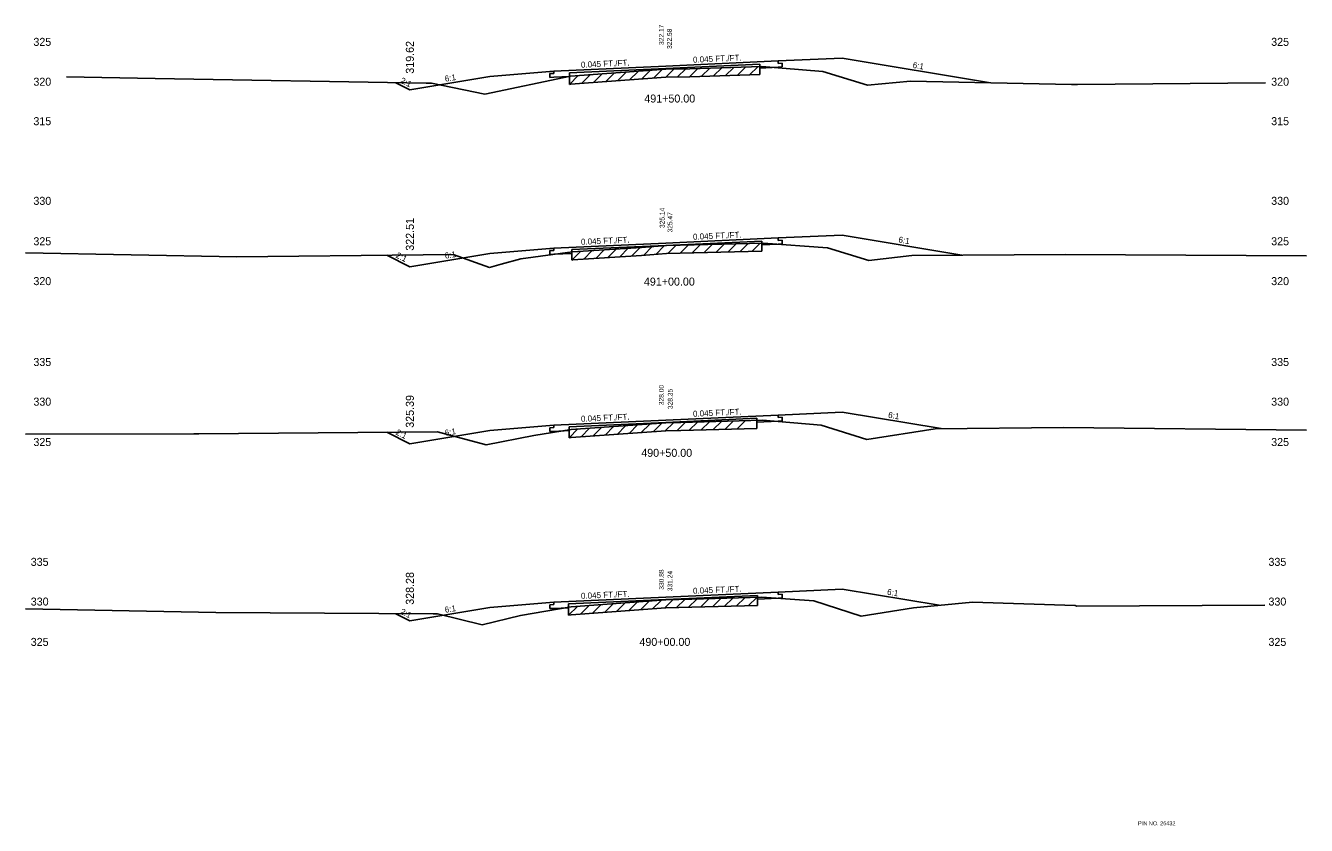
# Model space of a CAD drawing. Extents: x 883 to 1160, y 1002 to 4323.
# Drawn here: x 1000 to 1160, y 1102.7 to 1202.6 of the extents above; entities that cross this region are included whole.
import ezdxf

# ---------------------------------------------------------------- set-up
doc = ezdxf.new("R2010")
doc.units = 0
for name, color, linetype in [('Level 1', 7, 'Continuous'), ('Level 10', 7, 'Continuous'), ('Level 11', 7, 'Continuous'), ('Level 12', 7, 'Continuous'), ('Level 3', 7, 'Continuous'), ('Level 32', 7, 'Continuous'), ('Level 33', 7, 'Continuous'), ('Level 53', 7, 'Continuous'), ('Level 59', 7, 'Continuous'), ('Level 6', 7, 'Continuous'), ('Level 60', 7, 'Continuous'), ('Level 61', 7, 'Continuous'), ('Level 7', 7, 'Continuous')]:
    doc.layers.add(name, color=color, linetype=linetype)

msp = doc.modelspace()

# ---------------------------------------------------------------- linework, layer by layer
at = {"layer": 'Level 11'}
for p, q in [((1066, 1196.95), (1066, 1196.65)), ((1094, 1197.91), (1094, 1198.21)), ((1094.5, 1197.94), (1094, 1197.91)), ((1094, 1197.43), (1094.5, 1197.46)), ((1094.5, 1197.46), (1094.5, 1197.94)), ((1066, 1196.65), (1065.5, 1196.63)), ((1065.5, 1196.63), (1065.5, 1196.15)), ((1065.5, 1196.15), (1066, 1196.17)), ((1094, 1175.8), (1094, 1176.1)), ((1066, 1174.54), (1065.5, 1174.52)), ((1065.5, 1174.52), (1065.5, 1174.04)), ((1066, 1174.84), (1066, 1174.54)), ((1094.5, 1175.82), (1094, 1175.8)), ((1094, 1175.32), (1094.5, 1175.34)), ((1094.5, 1175.34), (1094.5, 1175.82)), ((1065.5, 1174.04), (1066, 1174.06)), ((1094, 1153.68), (1094, 1153.98)), ((1094.5, 1153.71), (1094, 1153.68)), ((1094.5, 1153.23), (1094.5, 1153.71)), ((1066, 1152.42), (1065.5, 1152.4)), ((1065.5, 1152.4), (1065.5, 1151.92)), ((1066, 1152.72), (1066, 1152.42)), ((1094, 1153.2), (1094.5, 1153.23)), ((1065.5, 1151.92), (1066, 1151.94)), ((1094, 1131.57), (1094, 1131.87)), ((1094.5, 1131.59), (1094, 1131.57)), ((1094.5, 1131.11), (1094.5, 1131.59)), ((1066, 1130.31), (1065.5, 1130.29)), ((1065.5, 1130.29), (1065.5, 1129.81)), ((1065.5, 1129.81), (1066, 1129.83)), ((1066, 1130.61), (1066, 1130.31)), ((1094, 1131.09), (1094.5, 1131.11))]:
    msp.add_line(p, q, dxfattribs=at)
at = {"layer": 'Level 12'}
for p, q in [((1091.74, 1197.51), (1091.74, 1197.33)), ((1091.74, 1197.33), (1094, 1197.43)), ((1067.94, 1196.26), (1066, 1196.17)), ((1067.94, 1196.28), (1067.94, 1196.26)), ((1091.96, 1175.45), (1091.96, 1175.23)), ((1091.96, 1175.23), (1094, 1175.32)), ((1068.22, 1174.16), (1066, 1174.06)), ((1068.22, 1174.34), (1068.22, 1174.16)), ((1067.89, 1152.03), (1066, 1151.94)), ((1067.89, 1152.13), (1067.89, 1152.03)), ((1091.36, 1153.32), (1091.36, 1153.09)), ((1091.36, 1153.09), (1094, 1153.2)), ((1091.41, 1131.2), (1091.41, 1130.97)), ((1067.82, 1129.91), (1066, 1129.83)), ((1067.82, 1129.97), (1067.82, 1129.91)), ((1091.41, 1130.97), (1094, 1131.09))]:
    msp.add_line(p, q, dxfattribs=at)
at = {"layer": 'Level 53'}
for p, q in [((1080, 1197.28), (1067.94, 1196.74)), ((1080, 1197.28), (1091.74, 1197.81)), ((1091.74, 1197.81), (1091.74, 1197.51)), ((1067.94, 1196.74), (1067.94, 1196.28)), ((1080, 1175.17), (1068.22, 1174.64)), ((1068.22, 1174.64), (1068.22, 1174.34)), ((1080, 1175.17), (1091.96, 1175.71)), ((1091.96, 1175.71), (1091.96, 1175.45)), ((1080, 1153.05), (1067.89, 1152.51)), ((1067.89, 1152.51), (1067.89, 1152.13)), ((1080, 1153.05), (1091.36, 1153.57)), ((1091.36, 1153.57), (1091.36, 1153.32)), ((1080, 1130.94), (1091.41, 1131.45)), ((1091.41, 1131.45), (1091.41, 1131.2)), ((1080, 1130.94), (1067.82, 1130.39)), ((1067.82, 1130.39), (1067.82, 1129.97))]:
    msp.add_line(p, q, dxfattribs=at)
at = {"layer": 'Level 59'}
for p, q in [((1066, 1196.95), (1080, 1197.58)), ((1080, 1197.58), (1094, 1198.21)), ((1080, 1175.47), (1094, 1176.1)), ((1066, 1174.84), (1080, 1175.47)), ((1080, 1153.35), (1094, 1153.98)), ((1066, 1152.72), (1080, 1153.35)), ((1066, 1130.61), (1080, 1131.24)), ((1080, 1131.24), (1094, 1131.87))]:
    msp.add_line(p, q, dxfattribs=at)
at = {"layer": 'Level 6'}
for p, q in [((1094, 1198.21), (1102, 1198.57)), ((1058, 1196.29), (1066, 1196.95)), ((1094, 1176.1), (1102, 1176.46)), ((1058, 1174.17), (1066, 1174.84)), ((1094, 1153.98), (1102, 1154.34)), ((1058, 1152.06), (1066, 1152.72)), ((1094, 1131.87), (1102, 1132.23)), ((1058, 1129.94), (1066, 1130.61))]:
    msp.add_line(p, q, dxfattribs=at)
at = {"layer": 'Level 60'}
for p, q in [((1068.05, 1196.3), (1080, 1197.17)), ((1080, 1197.17), (1082.97, 1197.25)), ((1082.97, 1197.25), (1091.97, 1197.52)), ((1091.97, 1197.52), (1099.59, 1196.9)), ((1099.59, 1196.9), (1105.18, 1195.19)), ((1005.12, 1196.22), (1016.19, 1196.04)), ((1016.19, 1196.04), (1050.02, 1195.43)), ((1050.02, 1195.43), (1050.7, 1195.42)), ((1050.7, 1195.42), (1057.37, 1194.06)), ((1057.37, 1194.06), (1068.05, 1196.3)), ((1105.18, 1195.19), (1110.56, 1195.68)), ((1110.56, 1195.68), (1130.65, 1195.29)), ((1130.65, 1195.29), (1131.42, 1195.28)), ((1131.42, 1195.28), (1154.89, 1195.47)), ((1068.33, 1174.35), (1076.93, 1174.93)), ((1076.93, 1174.93), (1080.06, 1175.14)), ((1080.06, 1175.14), (1092.13, 1175.45)), ((1092.13, 1175.45), (1100.17, 1174.86)), ((1100.17, 1174.86), (1105.35, 1173.27)), ((1000, 1174.26), (1026.38, 1173.76)), ((1026.38, 1173.76), (1049.66, 1173.99)), ((1049.66, 1173.99), (1053.43, 1174.03)), ((1053.43, 1174.03), (1057.97, 1172.41)), ((1057.97, 1172.41), (1059.41, 1172.81)), ((1059.41, 1172.81), (1061.86, 1173.5)), ((1061.86, 1173.5), (1068.33, 1174.35)), ((1105.35, 1173.27), (1110.72, 1173.93)), ((1110.72, 1173.93), (1129.85, 1174.03)), ((1129.85, 1174.03), (1160, 1173.88)), ((1063.49, 1151.42), (1068.16, 1152.18)), ((1068.16, 1152.18), (1080, 1153)), ((1080, 1153), (1081.85, 1153.05)), ((1081.85, 1153.05), (1092.04, 1153.34)), ((1092.04, 1153.34), (1099.38, 1152.72)), ((1099.38, 1152.72), (1105.07, 1150.94)), ((1105.07, 1150.94), (1113.62, 1152.27)), ((1113.62, 1152.27), (1129.64, 1152.41)), ((1129.64, 1152.41), (1160, 1152.09)), ((1000, 1151.58), (1021.01, 1151.64)), ((1021.01, 1151.64), (1021.62, 1151.63)), ((1021.62, 1151.63), (1051.47, 1151.89)), ((1051.47, 1151.89), (1057.55, 1150.25)), ((1057.55, 1150.25), (1063.49, 1151.42)), ((1083.23, 1130.97), (1091.96, 1131.22)), ((1091.96, 1131.22), (1098.47, 1130.79)), ((1000, 1129.76), (1023.77, 1129.32)), ((1061.84, 1128.93), (1068.15, 1130.03)), ((1068.15, 1130.03), (1080, 1130.88)), ((1080, 1130.88), (1083.23, 1130.97)), ((1098.47, 1130.79), (1104.4, 1128.85)), ((1104.4, 1128.85), (1110.9, 1129.89)), ((1110.9, 1129.89), (1118.31, 1130.61)), ((1118.31, 1130.61), (1131.1, 1130.2)), ((1131.1, 1130.2), (1131.32, 1130.09)), ((1131.32, 1130.09), (1154.83, 1130.24)), ((1023.77, 1129.32), (1050.93, 1129.13)), ((1050.93, 1129.13), (1051.47, 1129.13)), ((1051.47, 1129.13), (1057.02, 1127.76)), ((1057.02, 1127.76), (1061.84, 1128.93))]:
    msp.add_line(p, q, dxfattribs=at)
at = {"layer": 'Level 61'}
for p, q in [((1075.02, 1196.81), (1073.94, 1195.73)), ((1076.52, 1196.91), (1075.44, 1195.84)), ((1078.02, 1197.02), (1076.94, 1195.95)), ((1079.52, 1197.13), (1078.44, 1196.05)), ((1080.98, 1197.19), (1079.94, 1196.16)), ((1082.47, 1197.24), (1081.44, 1196.21)), ((1083.97, 1197.28), (1082.94, 1196.25)), ((1085.47, 1197.33), (1084.44, 1196.3)), ((1086.97, 1197.37), (1085.94, 1196.34)), ((1088.47, 1197.41), (1087.44, 1196.38)), ((1089.97, 1197.46), (1088.94, 1196.43)), ((1091.47, 1197.5), (1090.44, 1196.47)), ((1091.74, 1196.51), (1091.74, 1197.51)), ((1069.04, 1196.38), (1067.94, 1195.28)), ((1067.94, 1196.28), (1067.94, 1195.28)), ((1067.94, 1195.28), (1068.05, 1195.3)), ((1068.05, 1195.3), (1080, 1196.17)), ((1070.52, 1196.48), (1069.44, 1195.41)), ((1072.02, 1196.59), (1070.94, 1195.51)), ((1073.52, 1196.7), (1072.44, 1195.62)), ((1080, 1196.17), (1082.97, 1196.25)), ((1082.97, 1196.25), (1091.74, 1196.51)), ((1069.3, 1174.42), (1068.22, 1173.34)), ((1070.79, 1174.52), (1069.72, 1173.45)), ((1072.29, 1174.62), (1071.22, 1173.55)), ((1073.79, 1174.72), (1072.72, 1173.65)), ((1075.29, 1174.82), (1074.22, 1173.75)), ((1076.79, 1174.92), (1075.72, 1173.85)), ((1078.29, 1175.02), (1077.22, 1173.95)), ((1079.79, 1175.12), (1078.72, 1174.05)), ((1080.06, 1174.14), (1091.96, 1174.45)), ((1081.24, 1175.17), (1080.22, 1174.14)), ((1082.75, 1175.21), (1081.72, 1174.18)), ((1084.25, 1175.25), (1083.22, 1174.22)), ((1085.75, 1175.29), (1084.72, 1174.26)), ((1087.25, 1175.33), (1086.22, 1174.3)), ((1088.75, 1175.37), (1087.72, 1174.34)), ((1090.25, 1175.41), (1089.22, 1174.38)), ((1091.75, 1175.44), (1090.72, 1174.42)), ((1091.96, 1174.45), (1091.96, 1175.45)), ((1068.22, 1174.34), (1068.22, 1173.34)), ((1068.22, 1173.34), (1068.33, 1173.35)), ((1068.33, 1173.35), (1076.93, 1173.93)), ((1076.93, 1173.93), (1080.06, 1174.14)), ((1068.99, 1152.24), (1067.89, 1151.13)), ((1067.89, 1152.13), (1067.89, 1151.13)), ((1070.46, 1152.34), (1069.39, 1151.26)), ((1071.96, 1152.44), (1070.89, 1151.37)), ((1073.46, 1152.54), (1072.39, 1151.47)), ((1074.96, 1152.65), (1073.89, 1151.57)), ((1076.46, 1152.75), (1075.39, 1151.68)), ((1077.96, 1152.86), (1076.89, 1151.78)), ((1079.46, 1152.96), (1078.39, 1151.89)), ((1080.92, 1153.02), (1079.89, 1151.99)), ((1080, 1152), (1081.85, 1152.05)), ((1082.42, 1153.07), (1081.39, 1152.04)), ((1081.85, 1152.05), (1091.36, 1152.32)), ((1083.92, 1153.11), (1082.89, 1152.08)), ((1085.42, 1153.15), (1084.39, 1152.12)), ((1086.92, 1153.19), (1085.89, 1152.16)), ((1088.42, 1153.24), (1087.39, 1152.21)), ((1089.92, 1153.28), (1088.89, 1152.25)), ((1091.36, 1152.32), (1091.36, 1153.32)), ((1067.89, 1151.13), (1068.16, 1151.18)), ((1068.16, 1151.18), (1080, 1152)), ((1091.41, 1130.2), (1091.41, 1131.2)), ((1068.93, 1130.08), (1067.82, 1128.97)), ((1067.82, 1129.97), (1067.82, 1128.97)), ((1068.15, 1129.03), (1080, 1129.88)), ((1070.4, 1130.19), (1069.32, 1129.11)), ((1071.9, 1130.3), (1070.82, 1129.22)), ((1073.4, 1130.4), (1072.32, 1129.33)), ((1074.9, 1130.51), (1073.82, 1129.43)), ((1076.4, 1130.62), (1075.32, 1129.54)), ((1077.9, 1130.73), (1076.82, 1129.65)), ((1079.4, 1130.83), (1078.32, 1129.76)), ((1080.86, 1130.9), (1079.82, 1129.86)), ((1080, 1129.88), (1083.23, 1129.97)), ((1082.35, 1130.94), (1081.32, 1129.92)), ((1083.85, 1130.99), (1082.82, 1129.96)), ((1083.23, 1129.97), (1091.41, 1130.2)), ((1085.35, 1131.03), (1084.32, 1130)), ((1086.85, 1131.07), (1085.82, 1130.04)), ((1088.35, 1131.11), (1087.32, 1130.09)), ((1089.85, 1131.16), (1088.82, 1130.13)), ((1091.35, 1131.2), (1090.32, 1130.17)), ((1067.82, 1128.97), (1068.15, 1129.03))]:
    msp.add_line(p, q, dxfattribs=at)
at = {"layer": 'Level 7'}
for p, q in [((1102, 1198.57), (1120.52, 1195.49)), ((1046.25, 1195.49), (1048, 1194.62)), ((1048, 1194.62), (1058, 1196.29)), ((1102, 1176.46), (1116.96, 1173.97)), ((1045.12, 1173.94), (1048, 1172.51)), ((1048, 1172.51), (1058, 1174.17)), ((1102, 1154.34), (1114.39, 1152.28)), ((1048, 1150.39), (1058, 1152.06)), ((1045.11, 1151.84), (1048, 1150.39)), ((1102, 1132.23), (1114.14, 1130.21)), ((1048, 1128.28), (1058, 1129.94)), ((1046.23, 1129.16), (1048, 1128.28))]:
    msp.add_line(p, q, dxfattribs=at)

# ---------------------------------------------------------------- texts
at = {"layer": 'Level 1'}
for s, height, p in [('491+50.00', 1, (1077.29, 1193.02)), ('491+00.00', 1, (1077.24, 1170.15)), ('490+50.00', 1, (1076.91, 1148.76)), ('490+00.00', 1, (1076.68, 1125.14)), ('PIN NO. 26432', 0.5, (1138.97, 1102.73))]:
    msp.add_text(s, height=height, dxfattribs=at).set_placement(p)
at = {"layer": 'Level 10'}
for s, p in [('322.17', (1079.72, 1200.21)), ('325.14', (1079.82, 1177.34)), ('328.00', (1079.72, 1155.21)), ('330.88', (1079.72, 1132.16))]:
    msp.add_text(s, height=0.6, rotation=90, dxfattribs=at).set_placement(p)
at = {"layer": 'Level 3'}
for s, p in [(' 325', (1000.6, 1200.1)), (' 325', (1155.23, 1200.1)), (' 320', (1000.6, 1195.12)), (' 320', (1155.23, 1195.12)), (' 315', (1000.6, 1190.19)), (' 315', (1155.23, 1190.19)), (' 330', (1000.6, 1180.24)), (' 330', (1155.23, 1180.24)), (' 325', (1000.6, 1175.19)), (' 325', (1155.23, 1175.19)), (' 320', (1000.6, 1170.21)), (' 320', (1155.23, 1170.21)), (' 335', (1000.6, 1160.11)), (' 335', (1155.23, 1160.11)), (' 330', (1000.6, 1155.15)), (' 330', (1155.23, 1155.15)), (' 325', (1000.6, 1150.11)), (' 325', (1155.23, 1150.11)), (' 335', (1000.27, 1135.14)), (' 335', (1154.89, 1135.14)), (' 330', (1000.27, 1130.18)), (' 330', (1154.89, 1130.18)), (' 325', (1000.27, 1125.14)), (' 325', (1154.89, 1125.14))]:
    msp.add_text(s, height=1, dxfattribs=at).set_placement(p)
at = {"layer": 'Level 32'}
for s, rotation, p in [('0.045 FT./FT.', 2.5766, (1083.39, 1197.99)), ('0.045 FT./FT.', 2.5766, (1069.39, 1197.36)), ('6:1', 350.5377, (1110.78, 1197.36)), ('2:1', 333.435, (1046.73, 1195.53)), ('6:1', 9.4623, (1052.43, 1195.61)), ('0.045 FT./FT.', 2.5766, (1069.39, 1175.24)), ('0.045 FT./FT.', 2.5766, (1083.39, 1175.87)), ('6:1', 350.5377, (1109, 1175.55)), ('6:1', 9.4623, (1052.43, 1173.5)), ('2:1', 333.435, (1046.17, 1173.7)), ('0.045 FT./FT.', 2.5766, (1069.39, 1153.13)), ('0.045 FT./FT.', 2.5766, (1083.39, 1153.76)), ('6:1', 350.5377, (1107.71, 1153.65)), ('2:1', 333.435, (1046.16, 1151.59)), ('6:1', 9.4623, (1052.43, 1151.38)), ('0.045 FT./FT.', 2.5766, (1069.39, 1131.01)), ('0.045 FT./FT.', 2.5766, (1083.39, 1131.64)), ('6:1', 350.5377, (1107.58, 1131.55)), ('2:1', 333.435, (1046.72, 1129.19)), ('6:1', 9.4623, (1052.43, 1129.27))]:
    msp.add_text(s, height=0.75, rotation=rotation, dxfattribs=at).set_placement(p)
at = {"layer": 'Level 33'}
for s, p in [('319.62', (1048.5, 1196.62)), ('322.51', (1048.5, 1174.51)), ('325.39', (1048.5, 1152.39)), ('328.28', (1048.5, 1130.28))]:
    msp.add_text(s, height=1, rotation=90, dxfattribs=at).set_placement(p)
at = {"layer": 'Level 59'}
for s, p in [(' 322.58', (1080.73, 1199.49)), (' 325.47', (1080.8, 1176.56)), (' 328.35', (1080.83, 1154.49)), (' 331.24', (1080.8, 1131.74))]:
    msp.add_text(s, height=0.6, rotation=90, dxfattribs=at).set_placement(p)

doc.saveas('drawing.dxf')
